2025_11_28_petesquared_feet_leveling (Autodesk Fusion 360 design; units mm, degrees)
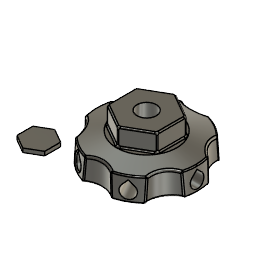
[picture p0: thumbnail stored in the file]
parameter "nut_diameter" = 14.478
parameter "nut_height" = 6.096
parameter "bolt_diameter" = 9.779
parameter "bottom_lip" = 11.43 (= "bottom - 0.45 in")
parameter "middle" = 8.89
parameter "bottom" = 22.86
parameter "top" = 0 (= "top_nut + 0.1 in")
parameter "top_nut" = -2.54
parameter "nut_cap_tollerance" = 0.2032
parameter "side_teardrop_diameter" = 6.858
parameter "bottom_ring_diameter" = 50.8
work_plane "WorkPlane5" AlongDistance 0 (= "top")
work_plane "WorkPlane4" AlongDistance -2.54 (= "top_nut")
work_plane "WorkPlane2"
work_plane "WorkPlane1"
work_plane "WorkPlane3"
sketch "top" plane through (0, 0, 0) normal (0, 0, 1) x axis (1, 0, 0)
  line L1 (7.239, 4.1794) -> (7.239, -4.1794)
  line L2 (0, 8.3589) -> (7.239, 4.1794)
  line L3 (-7.239, 4.1794) -> (0, 8.3589)
  line L4 (-7.239, -4.1794) -> (-7.239, 4.1794)
  line L5 (0, -8.3589) -> (-7.239, -4.1794)
  line L6 (7.239, -4.1794) -> (0, -8.3589)
  circle C1 centre (0, 0) radius 4.8895
  point P1 (0, 0)
  point P2 (0, 0)
  point P3 (0, 0)
  point P10 (0, 0)
  coincident P1 P2
  coincident P1 P3
  vertical L4
  coincident P3 P10
  dimension "d4" diameter C1 = 9.779 (= "bolt_diameter")
  dimension "d5" distance P10 L6 = 7.239 (= "nut_diameter / 2")
sketch "top_cylinder" plane through (0, 0, -8.89) normal (0, 0, 1) x axis (1, 0, 0)
  line L1 (12.7, 7.3323) -> (12.7, -7.3323)
  line L2 (0, 14.6647) -> (12.7, 7.3323)
  line L3 (-12.7, 7.3323) -> (0, 14.6647)
  line L4 (-12.7, -7.3323) -> (-12.7, 7.3323)
  line L5 (0, -14.6647) -> (-12.7, -7.3323)
  line L6 (12.7, -7.3323) -> (0, -14.6647)
  circle C1 centre (0, 0) radius 15.24
  point P1 (0, 0)
  point P2 (0, 0)
  point P9 (0, 0)
  coincident P1 P2
  coincident P1 P9
  vertical L4
  dimension "d17" diameter C1 = 30.48
  dimension "d26" distance P9 L6 = 12.7
sketch "bottom_lip" plane through (0, 0, -11.43) normal (0, 0, 1) x axis (1, 0, 0)
  circle C1 centre (0, 0) radius 25.4
  point P1 (0, 0)
  point P2 (0, 0)
  coincident P1 P2
  dimension "d7" diameter C1 = 50.8 (= "bottom_ring_diameter")
sketch "bottom" plane through (0, 0, -22.86) normal (0, 0, 1) x axis (1, 0, 0)
  circle C1 centre (0, 0) radius 26.035
  point P1 (0, 0)
  point P2 (0, 0)
  coincident P1 P2
  dimension "d22" diameter C1 = 52.07
loft "Loft2" sketch "bottom" + "bottom_lip"
loft "Loft3" sketch "bottom_lip" + "top_cylinder"
extrude "Extrude3" add sketch "top_cylinder" profile of L1 L2 L3 L4 L5 L6 to an object
extrude "Extrude4" add of existing geometry to an object
extrude "Extrude5" cut sketch "top" profile of C1 to an object taper 1.5 Side2Offset 0
extrude "Extrude6" sketch "top" blind 8.128 (= "nut_height + 0.08 in")
fillet "Fillet1" radius 0.635
extrude "Extrude7" sketch "top" blind 2.032 bodies "cap_nut"
offset_faces "OffsetFaces1"
work_plane "WorkPlane7" RotateAngle -30
work_plane "WorkPlane6" AlongDistance -26.67 (= "( ( -2 / 2 ) * 1 in ) - 0.05 in")
sketch "bottom_teardrop" plane through (-13.335, -23.0969, 0) normal (0.5, 0.866, 0) x axis (0.866, -0.5, 0)
  line L1 (0, 13.1847) -> (-2.4247, 15.6093)
  line L2 (2.4247, 15.6093) -> (0, 13.1847)
  line L3 (0, 18.034) -> (0, 13.1847)
  circle C1 centre (0, 18.034) radius 3.429
  point P2 (0, 18.034)
  point P3 (0, 22.86)
  point P4 (-2.4247, 15.6093)
  point P6 (2.4247, 15.6093)
  point P5 (0, 13.1847)
  point P7 (0, 18.034)
  vertical P2 P3
  coincident C1 P4
  coincident C1 P6
  tangent C1 L2
  tangent C1 L1
  vertical P2 P5
  coincident P2 P7
  dimension "d50" diameter C1 = 6.858 (= "side_teardrop_diameter")
  dimension "d51" distance P2 P3 = 4.826
  dimension "d52" angle L1 L3 = 45
extrude "Extrude8" cut sketch "bottom_teardrop" profile of C1 L1 L2 along a picked direction blind 17.78
fillet "Fillet3" radius 0.508
circular_pattern "C-Pattern1" TotalAngle 360
sketch "Sketch6" plane through (0, 0, -22.86) normal (0, 0, 1) x axis (1, 0, 0)
  circle C1 centre (0, -35.56) radius 12.7
  point P2 (0, -35.56)
  point P3 (0, 0)
  vertical P2 P3
  dimension "d58" distance P2 P3 = 35.56
  dimension "d59" diameter C1 = 25.4
extrude "Extrude9" cut sketch "Sketch6" to an object
fillet "Fillet2" radius 1.016
circular_pattern "C-Pattern2" TotalAngle 360
move "Move1"
named bodies: "base", "cap_nut"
